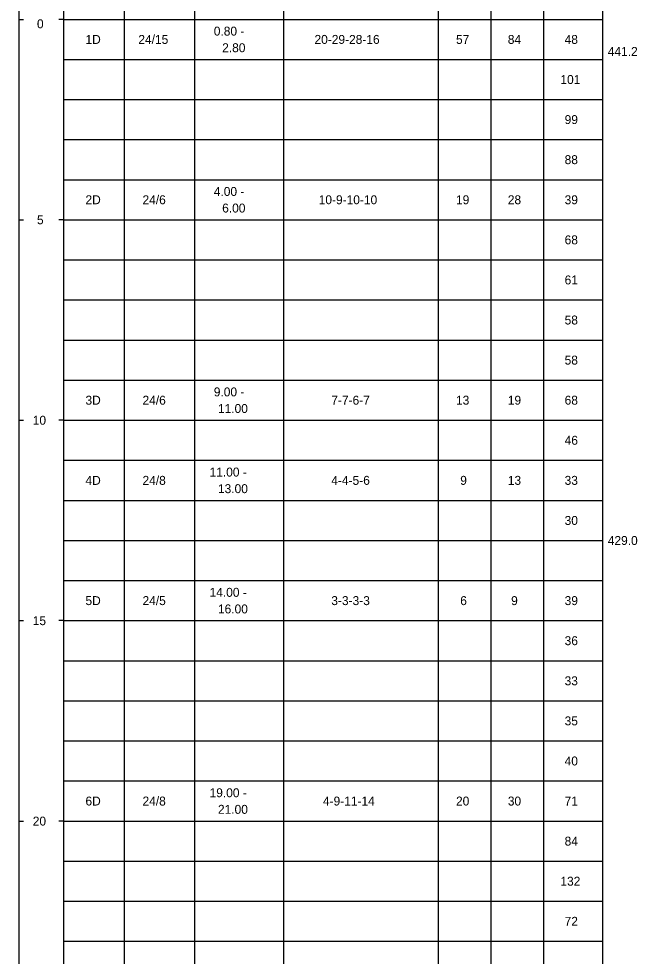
# Model space of a CAD drawing. Extents: x 9422 to 9552, y 6780 to 6860.
# Drawn here: x 9422.45 to 9437.86, y 6823.64 to 6847.03 of the extents above; entities that cross this region are included whole.
import ezdxf

# ---------------------------------------------------------------- set-up
doc = ezdxf.new("R2010")
doc.units = 0
doc.layers.add('7', color=7, linetype='Continuous')

msp = doc.modelspace()

# ---------------------------------------------------------------- linework, layer by layer
at = {"layer": '7'}
for points in [[(9422.449, 6860.114), (9422.449, 6821.983)], [(9423.567, 6850.528), (9423.567, 6821.983)], [(9425.076, 6849.992), (9425.076, 6821.983)], [(9426.831, 6849.992), (9426.831, 6821.983)], [(9429.046, 6849.992), (9429.046, 6821.983)], [(9432.901, 6849.992), (9432.901, 6821.983)], [(9434.213, 6849.992), (9434.213, 6821.983)], [(9435.526, 6849.992), (9435.526, 6821.983)], [(9437.002, 6849.992), (9437.002, 6821.983)], [(9422.449, 6847.011), (9422.571, 6847.011)], [(9423.567, 6847.011), (9423.445, 6847.011)], [(9423.567, 6847.011), (9425.076, 6847.011)], [(9425.076, 6847.011), (9426.831, 6847.011)], [(9426.831, 6847.011), (9429.046, 6847.011)], [(9429.046, 6847.011), (9432.901, 6847.011)], [(9432.901, 6847.011), (9434.213, 6847.011)], [(9434.213, 6847.011), (9435.526, 6847.011)], [(9435.526, 6847.011), (9437.002, 6847.011)], [(9423.567, 6846.011), (9425.076, 6846.011)], [(9425.076, 6846.011), (9426.831, 6846.011)], [(9426.831, 6846.011), (9429.046, 6846.011)], [(9429.046, 6846.011), (9432.901, 6846.011)], [(9432.901, 6846.011), (9434.213, 6846.011)], [(9434.213, 6846.011), (9435.526, 6846.011)], [(9435.526, 6846.011), (9437.002, 6846.011)], [(9423.567, 6845.011), (9425.076, 6845.011)], [(9425.076, 6845.011), (9426.831, 6845.011)], [(9426.831, 6845.011), (9429.046, 6845.011)], [(9429.046, 6845.011), (9432.901, 6845.011)], [(9432.901, 6845.011), (9434.213, 6845.011)], [(9434.213, 6845.011), (9435.526, 6845.011)], [(9435.526, 6845.011), (9437.002, 6845.011)], [(9423.567, 6844.011), (9425.076, 6844.011)], [(9425.076, 6844.011), (9426.831, 6844.011)], [(9426.831, 6844.011), (9429.046, 6844.011)], [(9429.046, 6844.011), (9432.901, 6844.011)], [(9432.901, 6844.011), (9434.213, 6844.011)], [(9434.213, 6844.011), (9435.526, 6844.011)], [(9435.526, 6844.011), (9437.002, 6844.011)], [(9423.567, 6843.011), (9425.076, 6843.011)], [(9425.076, 6843.011), (9426.831, 6843.011)], [(9426.831, 6843.011), (9429.046, 6843.011)], [(9429.046, 6843.011), (9432.901, 6843.011)], [(9432.901, 6843.011), (9434.213, 6843.011)], [(9434.213, 6843.011), (9435.526, 6843.011)], [(9435.526, 6843.011), (9437.002, 6843.011)], [(9422.449, 6842.011), (9422.571, 6842.011)], [(9423.567, 6842.011), (9423.445, 6842.011)], [(9423.567, 6842.011), (9425.076, 6842.011)], [(9425.076, 6842.011), (9426.831, 6842.011)], [(9426.831, 6842.011), (9429.046, 6842.011)], [(9429.046, 6842.011), (9432.901, 6842.011)], [(9432.901, 6842.011), (9434.213, 6842.011)], [(9434.213, 6842.011), (9435.526, 6842.011)], [(9435.526, 6842.011), (9437.002, 6842.011)], [(9423.567, 6841.011), (9425.076, 6841.011)], [(9425.076, 6841.011), (9426.831, 6841.011)], [(9426.831, 6841.011), (9429.046, 6841.011)], [(9429.046, 6841.011), (9432.901, 6841.011)], [(9432.901, 6841.011), (9434.213, 6841.011)], [(9434.213, 6841.011), (9435.526, 6841.011)], [(9435.526, 6841.011), (9437.002, 6841.011)], [(9423.567, 6840.011), (9425.076, 6840.011)], [(9425.076, 6840.011), (9426.831, 6840.011)], [(9426.831, 6840.011), (9429.046, 6840.011)], [(9429.046, 6840.011), (9432.901, 6840.011)], [(9432.901, 6840.011), (9434.213, 6840.011)], [(9434.213, 6840.011), (9435.526, 6840.011)], [(9435.526, 6840.011), (9437.002, 6840.011)], [(9423.567, 6839.011), (9425.076, 6839.011)], [(9425.076, 6839.011), (9426.831, 6839.011)], [(9426.831, 6839.011), (9429.046, 6839.011)], [(9429.046, 6839.011), (9432.901, 6839.011)], [(9432.901, 6839.011), (9434.213, 6839.011)], [(9434.213, 6839.011), (9435.526, 6839.011)], [(9435.526, 6839.011), (9437.002, 6839.011)], [(9423.567, 6838.011), (9425.076, 6838.011)], [(9425.076, 6838.011), (9426.831, 6838.011)], [(9426.831, 6838.011), (9429.046, 6838.011)], [(9429.046, 6838.011), (9432.901, 6838.011)], [(9432.901, 6838.011), (9434.213, 6838.011)], [(9434.213, 6838.011), (9435.526, 6838.011)], [(9435.526, 6838.011), (9437.002, 6838.011)], [(9422.449, 6837.011), (9422.571, 6837.011)], [(9423.567, 6837.011), (9423.445, 6837.011)], [(9423.567, 6837.011), (9425.076, 6837.011)], [(9425.076, 6837.011), (9426.831, 6837.011)], [(9426.831, 6837.011), (9429.046, 6837.011)], [(9429.046, 6837.011), (9432.901, 6837.011)], [(9432.901, 6837.011), (9434.213, 6837.011)], [(9434.213, 6837.011), (9435.526, 6837.011)], [(9435.526, 6837.011), (9437.002, 6837.011)], [(9423.567, 6836.011), (9425.076, 6836.011)], [(9425.076, 6836.011), (9426.831, 6836.011)], [(9426.831, 6836.011), (9429.046, 6836.011)], [(9429.046, 6836.011), (9432.901, 6836.011)], [(9432.901, 6836.011), (9434.213, 6836.011)], [(9434.213, 6836.011), (9435.526, 6836.011)], [(9435.526, 6836.011), (9437.002, 6836.011)], [(9423.567, 6835.011), (9425.076, 6835.011)], [(9425.076, 6835.011), (9426.831, 6835.011)], [(9426.831, 6835.011), (9429.046, 6835.011)], [(9429.046, 6835.011), (9432.901, 6835.011)], [(9432.901, 6835.011), (9434.213, 6835.011)], [(9434.213, 6835.011), (9435.526, 6835.011)], [(9435.526, 6835.011), (9437.002, 6835.011)], [(9423.567, 6834.011), (9425.076, 6834.011)], [(9425.076, 6834.011), (9426.831, 6834.011)], [(9426.831, 6834.011), (9429.046, 6834.011)], [(9429.046, 6834.011), (9432.901, 6834.011)], [(9432.901, 6834.011), (9434.213, 6834.011)], [(9434.213, 6834.011), (9435.526, 6834.011)], [(9435.526, 6834.011), (9437.002, 6834.011)], [(9423.567, 6833.011), (9425.076, 6833.011)], [(9425.076, 6833.011), (9426.831, 6833.011)], [(9426.831, 6833.011), (9429.046, 6833.011)], [(9429.046, 6833.011), (9432.901, 6833.011)], [(9432.901, 6833.011), (9434.213, 6833.011)], [(9434.213, 6833.011), (9435.526, 6833.011)], [(9435.526, 6833.011), (9437.002, 6833.011)], [(9422.449, 6832.011), (9422.571, 6832.011)], [(9423.567, 6832.011), (9423.445, 6832.011)], [(9423.567, 6832.011), (9425.076, 6832.011)], [(9425.076, 6832.011), (9426.831, 6832.011)], [(9426.831, 6832.011), (9429.046, 6832.011)], [(9429.046, 6832.011), (9432.901, 6832.011)], [(9432.901, 6832.011), (9434.213, 6832.011)], [(9434.213, 6832.011), (9435.526, 6832.011)], [(9435.526, 6832.011), (9437.002, 6832.011)], [(9423.567, 6831.011), (9425.076, 6831.011)], [(9425.076, 6831.011), (9426.831, 6831.011)], [(9426.831, 6831.011), (9429.046, 6831.011)], [(9429.046, 6831.011), (9432.901, 6831.011)], [(9432.901, 6831.011), (9434.213, 6831.011)], [(9434.213, 6831.011), (9435.526, 6831.011)], [(9435.526, 6831.011), (9437.002, 6831.011)], [(9423.567, 6830.011), (9425.076, 6830.011)], [(9425.076, 6830.011), (9426.831, 6830.011)], [(9426.831, 6830.011), (9429.046, 6830.011)], [(9429.046, 6830.011), (9432.901, 6830.011)], [(9432.901, 6830.011), (9434.213, 6830.011)], [(9434.213, 6830.011), (9435.526, 6830.011)], [(9435.526, 6830.011), (9437.002, 6830.011)], [(9423.567, 6829.011), (9425.076, 6829.011)], [(9425.076, 6829.011), (9426.831, 6829.011)], [(9426.831, 6829.011), (9429.046, 6829.011)], [(9429.046, 6829.011), (9432.901, 6829.011)], [(9432.901, 6829.011), (9434.213, 6829.011)], [(9434.213, 6829.011), (9435.526, 6829.011)], [(9435.526, 6829.011), (9437.002, 6829.011)], [(9423.567, 6828.011), (9425.076, 6828.011)], [(9425.076, 6828.011), (9426.831, 6828.011)], [(9426.831, 6828.011), (9429.046, 6828.011)], [(9429.046, 6828.011), (9432.901, 6828.011)], [(9432.901, 6828.011), (9434.213, 6828.011)], [(9434.213, 6828.011), (9435.526, 6828.011)], [(9435.526, 6828.011), (9437.002, 6828.011)], [(9422.449, 6827.011), (9422.571, 6827.011)], [(9423.567, 6827.011), (9423.445, 6827.011)], [(9423.567, 6827.011), (9425.076, 6827.011)], [(9425.076, 6827.011), (9426.831, 6827.011)], [(9426.831, 6827.011), (9429.046, 6827.011)], [(9429.046, 6827.011), (9432.901, 6827.011)], [(9432.901, 6827.011), (9434.213, 6827.011)], [(9434.213, 6827.011), (9435.526, 6827.011)], [(9435.526, 6827.011), (9437.002, 6827.011)], [(9423.567, 6826.011), (9425.076, 6826.011)], [(9425.076, 6826.011), (9426.831, 6826.011)], [(9426.831, 6826.011), (9429.046, 6826.011)], [(9429.046, 6826.011), (9432.901, 6826.011)], [(9432.901, 6826.011), (9434.213, 6826.011)], [(9434.213, 6826.011), (9435.526, 6826.011)], [(9435.526, 6826.011), (9437.002, 6826.011)], [(9423.567, 6825.011), (9425.076, 6825.011)], [(9425.076, 6825.011), (9426.831, 6825.011)], [(9426.831, 6825.011), (9429.046, 6825.011)], [(9429.046, 6825.011), (9432.901, 6825.011)], [(9432.901, 6825.011), (9434.213, 6825.011)], [(9434.213, 6825.011), (9435.526, 6825.011)], [(9435.526, 6825.011), (9437.002, 6825.011)], [(9423.567, 6824.011), (9425.076, 6824.011)], [(9425.076, 6824.011), (9426.831, 6824.011)], [(9426.831, 6824.011), (9429.046, 6824.011)], [(9429.046, 6824.011), (9432.901, 6824.011)], [(9432.901, 6824.011), (9434.213, 6824.011)], [(9434.213, 6824.011), (9435.526, 6824.011)], [(9435.526, 6824.011), (9437.002, 6824.011)]]:
    msp.add_lwpolyline(points, dxfattribs=at)

# ---------------------------------------------------------------- texts
for s, height, p in [('0', 0.223, (9422.903, 6846.788)), ('24/15', 0.2228, (9425.43, 6846.399)), ('0.80 -', 0.2228, (9427.31, 6846.606)), ('1D', 0.2228, (9424.112, 6846.399)), ('2.80', 0.2228, (9427.519, 6846.192)), ('20-29-28-16', 0.2228, (9429.82, 6846.399)), ('57', 0.2228, (9433.347, 6846.399)), (' 84', 0.2228, (9434.555, 6846.399)), ('48', 0.2228, (9436.054, 6846.399)), ('441.2', 0.2228, (9437.13, 6846.099)), ('101', 0.2228, (9435.949, 6845.399)), ('99', 0.2228, (9436.054, 6844.399)), ('88', 0.2228, (9436.054, 6843.399)), ('4.00 -', 0.2228, (9427.31, 6842.606)), ('2D', 0.2228, (9424.112, 6842.399)), ('24/6', 0.2228, (9425.534, 6842.399)), ('10-9-10-10', 0.2228, (9429.925, 6842.399)), ('19', 0.2228, (9433.347, 6842.399)), (' 28', 0.2228, (9434.555, 6842.399)), ('39', 0.2228, (9436.054, 6842.399)), ('6.00', 0.2228, (9427.519, 6842.192)), ('5', 0.223, (9422.903, 6841.899)), ('68', 0.2228, (9436.054, 6841.399)), ('61', 0.2228, (9436.054, 6840.399)), ('58', 0.2228, (9436.054, 6839.399)), ('58', 0.2228, (9436.054, 6838.399)), ('9.00 -', 0.2228, (9427.31, 6837.606)), ('3D', 0.2228, (9424.112, 6837.399)), ('24/6', 0.2228, (9425.534, 6837.399)), ('7-7-6-7', 0.2228, (9430.239, 6837.399)), ('13', 0.2228, (9433.347, 6837.399)), (' 19', 0.2228, (9434.555, 6837.399)), ('68', 0.2228, (9436.054, 6837.399)), ('11.00', 0.2228, (9427.414, 6837.192)), ('10', 0.2228, (9422.798, 6836.899)), ('46', 0.2228, (9436.054, 6836.399)), ('11.00 -', 0.2228, (9427.205, 6835.606)), ('4D', 0.2228, (9424.112, 6835.399)), ('24/8', 0.2228, (9425.534, 6835.399)), ('13.00', 0.2228, (9427.414, 6835.192)), ('4-4-5-6', 0.2228, (9430.239, 6835.399)), ('9', 0.223, (9433.452, 6835.399)), (' 13', 0.2228, (9434.555, 6835.399)), ('33', 0.2228, (9436.054, 6835.399)), ('30', 0.2228, (9436.054, 6834.399)), ('429.0', 0.2228, (9437.13, 6833.899)), ('5D', 0.2228, (9424.112, 6832.399)), ('24/5', 0.2228, (9425.534, 6832.399)), ('14.00 -', 0.2228, (9427.205, 6832.606)), ('3-3-3-3', 0.2228, (9430.239, 6832.399)), ('6', 0.223, (9433.452, 6832.399)), ('  9', 0.2228, (9434.555, 6832.399)), ('39', 0.2228, (9436.054, 6832.399)), ('16.00', 0.2228, (9427.414, 6832.192)), ('15', 0.2228, (9422.798, 6831.899)), ('36', 0.2228, (9436.054, 6831.399)), ('33', 0.2228, (9436.054, 6830.399)), ('35', 0.2228, (9436.054, 6829.399)), ('40', 0.2228, (9436.054, 6828.399)), ('19.00 -', 0.2228, (9427.205, 6827.606)), ('6D', 0.2228, (9424.112, 6827.399)), ('24/8', 0.2228, (9425.534, 6827.399)), ('4-9-11-14', 0.2228, (9430.03, 6827.399)), ('20', 0.2228, (9433.347, 6827.399)), (' 30', 0.2228, (9434.555, 6827.399)), ('71', 0.2228, (9436.054, 6827.399)), ('21.00', 0.2228, (9427.414, 6827.192)), ('20', 0.2228, (9422.798, 6826.899)), ('84', 0.2228, (9436.054, 6826.399)), ('132', 0.2228, (9435.949, 6825.399)), ('72', 0.2228, (9436.054, 6824.399))]:
    msp.add_text(s, height=height, dxfattribs=at).set_placement(p)

doc.saveas('drawing.dxf')
